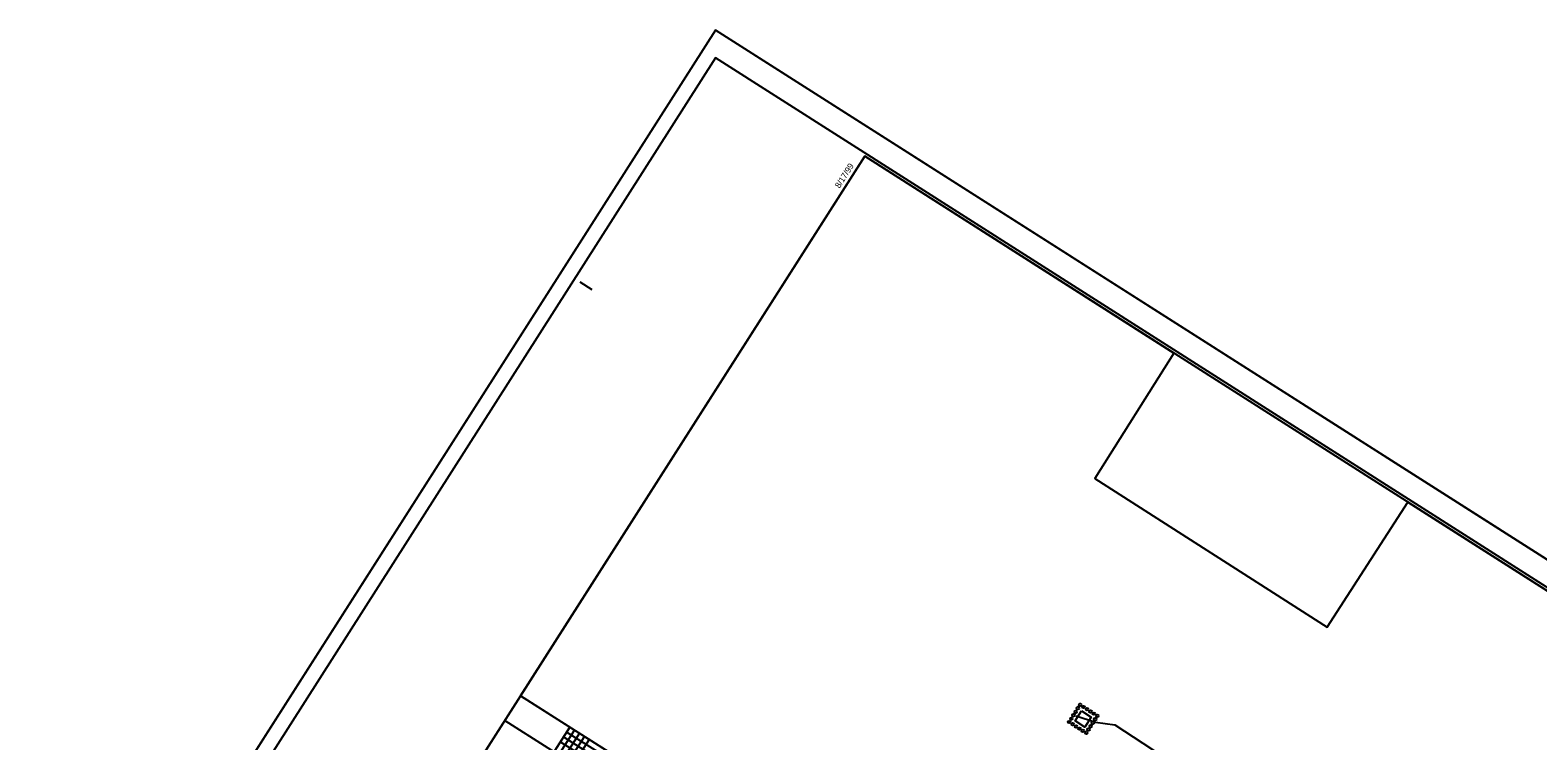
# Model space of a CAD drawing. Extents: x 2023536 to 2025544, y 819438 to 821266.
# Drawn here: x 2023536 to 2024831, y 820655 to 821266 of the extents above; entities that cross this region are included whole.
import ezdxf

# ---------------------------------------------------------------- set-up
doc = ezdxf.new("R2010")
doc.units = 0
for name, color, linetype in [('Rock Inlet Sediment Trap Type C Final CELL', 7, 'Continuous'), ('Sheet Clip Boundary CELL', 7, 'Continuous'), ('Sheet Cutting Line CELL', 7, 'Continuous'), ('Sheet DOT Grid CELL', 7, 'Continuous'), ('Sheet Layout Profile Border Port 2', 7, 'Continuous'), ('Sheet Plan And Profile CELL', 7, 'Continuous'), ('Sheet Plot Border Inside CELL', 7, 'Continuous'), ('Sheet Plot Border Outside CELL', 7, 'Continuous'), ('Sheet Profile Grid Major CELL', 7, 'Continuous'), ('Sheet Profile Grid Middle CELL', 7, 'Continuous'), ('Sheet Profile Grid Minor CELL', 7, 'Continuous'), ('Temporary Silt Fence Both', 7, 'Continuous'), ('Temporary Silt Fence CG', 7, 'Continuous')]:
    doc.layers.add(name, color=color, linetype=linetype)

msp = doc.modelspace()

# ---------------------------------------------------------------- linework, layer by layer
at = {"layer": 'Rock Inlet Sediment Trap Type C Final CELL'}
msp.add_lwpolyline([(2024439.1, 820681), (2024447.5, 820675.7), (2024442.1, 820667.2), (2024433.7, 820672.6)], close=True, dxfattribs=at)
for centre in [(2024430.4, 820674.4), (2024432.3, 820677.4), (2024434.1, 820680.3), (2024436, 820683.3), (2024437.9, 820686.2), (2024440.9, 820684.4), (2024443.8, 820682.5), (2024446.8, 820680.6), (2024449.7, 820678.7), (2024450.8, 820673.9), (2024452.7, 820676.8), (2024428.5, 820671.5), (2024431.5, 820669.6), (2024434.4, 820667.7), (2024437.4, 820665.8), (2024440.3, 820664), (2024443.3, 820662.1), (2024445.1, 820665), (2024447, 820668), (2024448.9, 820670.9)]:
    msp.add_circle(centre, 1.12, dxfattribs=at)
at = {"layer": 'Sheet Clip Boundary CELL'}
msp.add_lwpolyline([(2023957.3, 820694), (2024252.9, 821157.8), (2024518.4, 820988.6), (2024450.6, 820880.9), (2024650, 820753), (2024719.3, 820860.6), (2025349.2, 820459.2), (2025268.5, 820332.6), (2025437.2, 820225.1), (2025222.2, 819887.8)], close=True, dxfattribs=at)
at = {"layer": 'Sheet Cutting Line CELL'}
for p, q in [((2024124.6, 821266.3), (2023536.1, 820342.9)), ((2025544.3, 820361.5), (2024124.6, 821266.3))]:
    msp.add_line(p, q, dxfattribs=at)
at = {"layer": 'Sheet DOT Grid CELL'}
for p, q in [((2023957.3, 820694), (2024041.6, 820640.3)), ((2023999.5, 820667.1), (2023744.2, 820266.6))]:
    msp.add_line(p, q, dxfattribs=at)
at = {"layer": 'Sheet Layout Profile Border Port 2'}
msp.add_lwpolyline([(2024716.3, 820210.3), (2025180.1, 819914.7), (2024924.8, 819514.1), (2023744.2, 820266.6), (2023999.5, 820667.1), (2024041.6, 820640.3)], dxfattribs=at)
at = {"layer": 'Sheet Plan And Profile CELL'}
msp.add_line((2024008.1, 821050), (2024018.6, 821043.3), dxfattribs=at)
msp.add_lwpolyline([(2025517.9, 820351.6), (2024252.9, 821157.8), (2023688.6, 820272.4), (2024953.5, 819466.2)], close=True, dxfattribs=at)
at = {"layer": 'Sheet Plot Border Inside CELL'}
msp.add_lwpolyline([(2023557.8, 820352.8), (2024962.7, 819457.4), (2025529.7, 820347), (2024124.8, 821242.4)], close=True, dxfattribs=at)
at = {"layer": 'Sheet Plot Border Outside CELL'}
msp.add_lwpolyline([(2023536.1, 820342.9), (2024955.8, 819438.1), (2025544.3, 820361.5), (2024124.6, 821266.3)], close=True, dxfattribs=at)
at = {"layer": 'Sheet Profile Grid Major CELL'}
for points in [[(2023957.3, 820694), (2023702, 820293.5)], [(2023957.3, 820694), (2024041.6, 820640.3)], [(2023744.2, 820266.6), (2023999.5, 820667.1), (2024041.6, 820640.3)]]:
    msp.add_lwpolyline(points, dxfattribs=at)
at = {"layer": 'Sheet Profile Grid Middle CELL'}
msp.add_line((2023943.9, 820672.9), (2024028.2, 820619.2), dxfattribs=at)
at = {"layer": 'Sheet Profile Grid Minor CELL'}
for points in [[(2023748.4, 820263.9), (2024003.7, 820664.5), (2024007.9, 820661.8), (2023752.6, 820261.2)], [(2024039, 820636.1), (2023996.8, 820662.9)], [(2023756.8, 820258.5), (2024012.1, 820659.1), (2024016.3, 820656.4), (2023761.1, 820255.8)], [(2024033.6, 820627.6), (2023991.4, 820654.5), (2023994.1, 820658.7), (2024036.3, 820631.8)]]:
    msp.add_lwpolyline(points, dxfattribs=at)
at = {"layer": 'Temporary Silt Fence Both'}
msp.add_lwpolyline([(2024451.2, 820671.4), (2024467.7, 820669), (2024491.7, 820653.2), (2024516.2, 820637.2), (2024532.3, 820626.9), (2024574.2, 820608.6), (2024610.4, 820591.4), (2024632.4, 820580)], dxfattribs=at)
at = {"layer": 'Temporary Silt Fence CG'}
msp.add_line((2024434.6, 820676.9), (2024451.2, 820671.4), dxfattribs=at)

# ---------------------------------------------------------------- texts
at = {"layer": 'Sheet Plan And Profile CELL'}
msp.add_text('8/17/99', height=5.25, rotation=57.4893, dxfattribs=at).set_placement((2024231.3, 821129.9))

doc.saveas('drawing.dxf')
